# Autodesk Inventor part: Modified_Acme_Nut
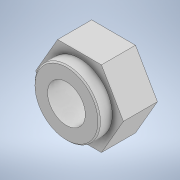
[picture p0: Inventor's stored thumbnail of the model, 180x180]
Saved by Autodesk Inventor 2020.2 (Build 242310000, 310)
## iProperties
Created: 2019-12
Part Number: Modified_Acme_Nut
Material: Generic
Document SubType Name: Modeling
Designer: Patrick Everitt
Density: 1 g/cm^3
Appearance: Default
Author: Patrick Everitt
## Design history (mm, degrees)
sketch "Sketch1"
  geometry: L1 (13.29, 23.019)-(26.58, 0); L2 (26.58, 0)-(13.29, -23.019); L3 (13.29, -23.019)-(-13.29, -23.019); L4 (-13.29, -23.019)-(-26.58, 0); L5 (-26.58, 0)-(-13.29, 23.019); L6 (-13.29, 23.019)-(13.29, 23.019); C1 r 11.43 at (0, 0); 2 further points
  constraints: 12 end point, 3 coincident, 1 centre point, 1 horizontal, 13 other
  dimensions: "d0" = 46.0375 distance between parallel lines of L3 L6; "d1" = 22.86 diameter of C1
extrude "Extrusion1" new body sketch "Sketch1" distance "d2" = 28.575; taper "d3" = 0 deg
sketch "Sketch2"
  geometry: C1 r 19.844 at (0, 0); C2 r 27.781 at (0, 0); 1 further point
  constraints: 2 centre point, 2 coincident
  dimensions: "d4" = 39.6875 diameter of C1; "d5" = 55.5625 diameter of C2
extrude "Extrusion2" cut sketch "Sketch2" distance "d6" = 7.9375; taper "d7" = 0 deg
chamfer "Chamfer1" distance "d8" = 0.762; stored, may be unused: second distance "d9" = 3.175, angle "d10" = 45 deg
body "Solid1"
